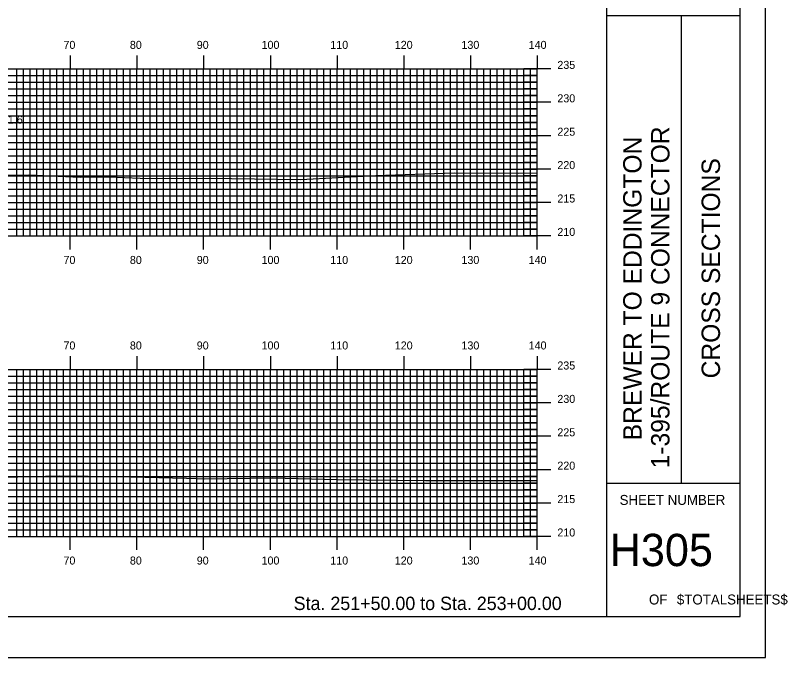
# Model space of a CAD drawing. Extents: x 1804290 to 1804634, y 442591 to 442811.
# Drawn here: x 1804518 to 1804633.7, y 442590.5 to 442686.7 of the extents above; entities that cross this region are included whole.
import ezdxf

# ---------------------------------------------------------------- set-up
doc = ezdxf.new("R2010")
doc.units = 0
for name, color, linetype in [('BORDER', 7, 'Continuous'), ('D_Text_Standard', 7, 'Continuous'), ('H_V ANNOTATION', 7, 'Continuous'), ('MAJOR', 7, 'Continuous'), ('MINOR', 7, 'Continuous'), ('PLOT BOUNDARY', 7, 'Continuous'), ('S_Roadway_Centerline', 7, 'Continuous')]:
    doc.layers.add(name, color=color, linetype=linetype)

msp = doc.modelspace()

# ---------------------------------------------------------------- linework, layer by layer
at = {"layer": 'BORDER'}
for p, q in [((1804606.57, 442596.67), (1804606.57, 442806.67)), ((1804606.57, 442686.67), (1804626.57, 442686.67)), ((1804617.75, 442616.67), (1804617.75, 442686.67)), ((1804606.57, 442616.67), (1804626.57, 442616.67))]:
    msp.add_line(p, q, dxfattribs=at)
msp.add_lwpolyline([(1804306.57, 442596.67), (1804626.57, 442596.67), (1804626.57, 442806.67), (1804306.57, 442806.67)], close=True, dxfattribs=at)
at = {"layer": 'MAJOR'}
for p, q in [((1804526.17, 442680.67), (1804526.17, 442678.67)), ((1804536.17, 442680.67), (1804536.17, 442678.67)), ((1804546.17, 442680.67), (1804546.17, 442678.67)), ((1804556.17, 442680.67), (1804556.17, 442678.67)), ((1804566.17, 442680.67), (1804566.17, 442678.67)), ((1804576.17, 442680.67), (1804576.17, 442678.67)), ((1804586.17, 442680.67), (1804586.17, 442678.67)), ((1804596.17, 442680.67), (1804596.17, 442678.67)), ((1804316.17, 442678.67), (1804596.17, 442678.67)), ((1804316.17, 442678.67), (1804596.17, 442678.67)), ((1804526.17, 442653.67), (1804526.17, 442678.67)), ((1804536.17, 442653.67), (1804536.17, 442678.67)), ((1804546.17, 442653.67), (1804546.17, 442678.67)), ((1804556.17, 442653.67), (1804556.17, 442678.67)), ((1804566.17, 442653.67), (1804566.17, 442678.67)), ((1804576.17, 442653.67), (1804576.17, 442678.67)), ((1804586.17, 442653.67), (1804586.17, 442678.67)), ((1804598.17, 442678.67), (1804594.16, 442678.67)), ((1804596.17, 442653.67), (1804596.17, 442678.67)), ((1804596.17, 442653.67), (1804596.17, 442678.67)), ((1804316.17, 442673.67), (1804596.17, 442673.67)), ((1804598.17, 442673.67), (1804594.16, 442673.67)), ((1804316.17, 442668.67), (1804596.17, 442668.67)), ((1804598.17, 442668.67), (1804594.16, 442668.67)), ((1804316.17, 442663.67), (1804596.17, 442663.67)), ((1804598.17, 442663.67), (1804594.16, 442663.67)), ((1804316.17, 442658.67), (1804596.17, 442658.67)), ((1804598.17, 442658.67), (1804594.16, 442658.67)), ((1804316.17, 442653.67), (1804596.17, 442653.67)), ((1804316.17, 442653.67), (1804596.17, 442653.67)), ((1804526.17, 442651.66), (1804526.17, 442653.67)), ((1804536.17, 442651.66), (1804536.17, 442653.67)), ((1804546.17, 442651.66), (1804546.17, 442653.67)), ((1804556.17, 442651.66), (1804556.17, 442653.67)), ((1804566.17, 442651.66), (1804566.17, 442653.67)), ((1804576.17, 442651.66), (1804576.17, 442653.67)), ((1804586.17, 442651.66), (1804586.17, 442653.67)), ((1804598.17, 442653.67), (1804594.16, 442653.67)), ((1804596.17, 442651.66), (1804596.17, 442653.67)), ((1804526.17, 442635.67), (1804526.17, 442633.67)), ((1804536.17, 442635.67), (1804536.17, 442633.67)), ((1804546.17, 442635.67), (1804546.17, 442633.67)), ((1804556.17, 442635.67), (1804556.17, 442633.67)), ((1804566.17, 442635.67), (1804566.17, 442633.67)), ((1804576.17, 442635.67), (1804576.17, 442633.67)), ((1804586.17, 442635.67), (1804586.17, 442633.67)), ((1804596.17, 442635.67), (1804596.17, 442633.67)), ((1804316.17, 442633.67), (1804596.17, 442633.67)), ((1804316.17, 442633.67), (1804596.17, 442633.67)), ((1804526.17, 442608.67), (1804526.17, 442633.67)), ((1804536.17, 442608.67), (1804536.17, 442633.67)), ((1804546.17, 442608.67), (1804546.17, 442633.67)), ((1804556.17, 442608.67), (1804556.17, 442633.67)), ((1804566.17, 442608.67), (1804566.17, 442633.67)), ((1804576.17, 442608.67), (1804576.17, 442633.67)), ((1804586.17, 442608.67), (1804586.17, 442633.67)), ((1804598.17, 442633.67), (1804594.16, 442633.67)), ((1804596.17, 442608.67), (1804596.17, 442633.67)), ((1804596.17, 442608.67), (1804596.17, 442633.67)), ((1804316.17, 442628.67), (1804596.17, 442628.67)), ((1804598.17, 442628.67), (1804594.16, 442628.67)), ((1804316.17, 442623.67), (1804596.17, 442623.67)), ((1804598.17, 442623.67), (1804594.16, 442623.67)), ((1804316.17, 442618.67), (1804596.17, 442618.67)), ((1804598.17, 442618.67), (1804594.16, 442618.67)), ((1804316.17, 442613.67), (1804596.17, 442613.67)), ((1804598.17, 442613.67), (1804594.16, 442613.67)), ((1804316.17, 442608.67), (1804596.17, 442608.67)), ((1804316.17, 442608.67), (1804596.17, 442608.67)), ((1804526.17, 442606.66), (1804526.17, 442608.67)), ((1804536.17, 442606.66), (1804536.17, 442608.67)), ((1804546.17, 442606.66), (1804546.17, 442608.67)), ((1804556.17, 442606.66), (1804556.17, 442608.67)), ((1804566.17, 442606.66), (1804566.17, 442608.67)), ((1804576.17, 442606.66), (1804576.17, 442608.67)), ((1804586.17, 442606.66), (1804586.17, 442608.67)), ((1804598.17, 442608.67), (1804594.16, 442608.67)), ((1804596.17, 442606.66), (1804596.17, 442608.67))]:
    msp.add_line(p, q, dxfattribs=at)
at = {"layer": 'MINOR'}
for p, q in [((1804316.17, 442677.67), (1804596.17, 442677.67)), ((1804518.17, 442653.67), (1804518.17, 442678.67)), ((1804519.17, 442653.67), (1804519.17, 442678.67)), ((1804520.17, 442653.67), (1804520.17, 442678.67)), ((1804521.17, 442653.67), (1804521.17, 442678.67)), ((1804522.17, 442653.67), (1804522.17, 442678.67)), ((1804523.17, 442653.67), (1804523.17, 442678.67)), ((1804524.17, 442653.67), (1804524.17, 442678.67)), ((1804525.17, 442653.67), (1804525.17, 442678.67)), ((1804527.17, 442653.67), (1804527.17, 442678.67)), ((1804528.17, 442653.67), (1804528.17, 442678.67)), ((1804529.17, 442653.67), (1804529.17, 442678.67)), ((1804530.17, 442653.67), (1804530.17, 442678.67)), ((1804531.17, 442653.67), (1804531.17, 442678.67)), ((1804532.17, 442653.67), (1804532.17, 442678.67)), ((1804533.17, 442653.67), (1804533.17, 442678.67)), ((1804534.17, 442653.67), (1804534.17, 442678.67)), ((1804535.17, 442653.67), (1804535.17, 442678.67)), ((1804537.17, 442653.67), (1804537.17, 442678.67)), ((1804538.17, 442653.67), (1804538.17, 442678.67)), ((1804539.17, 442653.67), (1804539.17, 442678.67)), ((1804540.17, 442653.67), (1804540.17, 442678.67)), ((1804541.17, 442653.67), (1804541.17, 442678.67)), ((1804542.17, 442653.67), (1804542.17, 442678.67)), ((1804543.17, 442653.67), (1804543.17, 442678.67)), ((1804544.17, 442653.67), (1804544.17, 442678.67)), ((1804545.17, 442653.67), (1804545.17, 442678.67)), ((1804547.17, 442653.67), (1804547.17, 442678.67)), ((1804548.17, 442653.67), (1804548.17, 442678.67)), ((1804549.17, 442653.67), (1804549.17, 442678.67)), ((1804550.17, 442653.67), (1804550.17, 442678.67)), ((1804551.17, 442653.67), (1804551.17, 442678.67)), ((1804552.17, 442653.67), (1804552.17, 442678.67)), ((1804553.17, 442653.67), (1804553.17, 442678.67)), ((1804554.17, 442653.67), (1804554.17, 442678.67)), ((1804555.17, 442653.67), (1804555.17, 442678.67)), ((1804557.17, 442653.67), (1804557.17, 442678.67)), ((1804558.17, 442653.67), (1804558.17, 442678.67)), ((1804559.17, 442653.67), (1804559.17, 442678.67)), ((1804560.17, 442653.67), (1804560.17, 442678.67)), ((1804561.17, 442653.67), (1804561.17, 442678.67)), ((1804562.17, 442653.67), (1804562.17, 442678.67)), ((1804563.17, 442653.67), (1804563.17, 442678.67)), ((1804564.17, 442653.67), (1804564.17, 442678.67)), ((1804565.17, 442653.67), (1804565.17, 442678.67)), ((1804567.17, 442653.67), (1804567.17, 442678.67)), ((1804568.17, 442653.67), (1804568.17, 442678.67)), ((1804569.17, 442653.67), (1804569.17, 442678.67)), ((1804570.17, 442653.67), (1804570.17, 442678.67)), ((1804571.17, 442653.67), (1804571.17, 442678.67)), ((1804572.17, 442653.67), (1804572.17, 442678.67)), ((1804573.17, 442653.67), (1804573.17, 442678.67)), ((1804574.17, 442653.67), (1804574.17, 442678.67)), ((1804575.17, 442653.67), (1804575.17, 442678.67)), ((1804577.17, 442653.67), (1804577.17, 442678.67)), ((1804578.17, 442653.67), (1804578.17, 442678.67)), ((1804579.17, 442653.67), (1804579.17, 442678.67)), ((1804580.17, 442653.67), (1804580.17, 442678.67)), ((1804581.17, 442653.67), (1804581.17, 442678.67)), ((1804582.17, 442653.67), (1804582.17, 442678.67)), ((1804583.17, 442653.67), (1804583.17, 442678.67)), ((1804584.17, 442653.67), (1804584.17, 442678.67)), ((1804585.17, 442653.67), (1804585.17, 442678.67)), ((1804587.17, 442653.67), (1804587.17, 442678.67)), ((1804588.17, 442653.67), (1804588.17, 442678.67)), ((1804589.17, 442653.67), (1804589.17, 442678.67)), ((1804590.17, 442653.67), (1804590.17, 442678.67)), ((1804591.17, 442653.67), (1804591.17, 442678.67)), ((1804592.17, 442653.67), (1804592.17, 442678.67)), ((1804593.17, 442653.67), (1804593.17, 442678.67)), ((1804596.17, 442677.67), (1804594.16, 442677.67)), ((1804594.17, 442653.67), (1804594.17, 442678.67)), ((1804595.17, 442653.67), (1804595.17, 442678.67)), ((1804316.17, 442676.67), (1804596.17, 442676.67)), ((1804596.17, 442676.67), (1804594.16, 442676.67)), ((1804316.17, 442675.67), (1804596.17, 442675.67)), ((1804596.17, 442675.67), (1804594.16, 442675.67)), ((1804316.17, 442674.67), (1804596.17, 442674.67)), ((1804596.17, 442674.67), (1804594.16, 442674.67)), ((1804316.17, 442672.67), (1804596.17, 442672.67)), ((1804596.17, 442672.67), (1804594.16, 442672.67)), ((1804316.17, 442671.67), (1804596.17, 442671.67)), ((1804316.17, 442670.67), (1804596.17, 442670.67)), ((1804596.17, 442671.67), (1804594.16, 442671.67)), ((1804596.17, 442670.67), (1804594.16, 442670.67)), ((1804316.17, 442669.67), (1804596.17, 442669.67)), ((1804596.17, 442669.67), (1804594.16, 442669.67)), ((1804316.17, 442667.67), (1804596.17, 442667.67)), ((1804596.17, 442667.67), (1804594.16, 442667.67)), ((1804316.17, 442666.67), (1804596.17, 442666.67)), ((1804596.17, 442666.67), (1804594.16, 442666.67)), ((1804316.17, 442665.67), (1804596.17, 442665.67)), ((1804596.17, 442665.67), (1804594.16, 442665.67)), ((1804316.17, 442664.67), (1804596.17, 442664.67)), ((1804596.17, 442664.67), (1804594.16, 442664.67)), ((1804316.17, 442662.67), (1804596.17, 442662.67)), ((1804596.17, 442662.67), (1804594.16, 442662.67)), ((1804316.17, 442661.67), (1804596.17, 442661.67)), ((1804596.17, 442661.67), (1804594.16, 442661.67)), ((1804316.17, 442660.67), (1804596.17, 442660.67)), ((1804596.17, 442660.67), (1804594.16, 442660.67)), ((1804316.17, 442659.67), (1804596.17, 442659.67)), ((1804596.17, 442659.67), (1804594.16, 442659.67)), ((1804316.17, 442657.67), (1804596.17, 442657.67)), ((1804596.17, 442657.67), (1804594.16, 442657.67)), ((1804316.17, 442656.67), (1804596.17, 442656.67)), ((1804316.17, 442655.67), (1804596.17, 442655.67)), ((1804596.17, 442656.67), (1804594.16, 442656.67)), ((1804596.17, 442655.67), (1804594.16, 442655.67)), ((1804316.17, 442654.67), (1804596.17, 442654.67)), ((1804596.17, 442654.67), (1804594.16, 442654.67)), ((1804518.17, 442608.67), (1804518.17, 442633.67)), ((1804519.17, 442608.67), (1804519.17, 442633.67)), ((1804520.17, 442608.67), (1804520.17, 442633.67)), ((1804521.17, 442608.67), (1804521.17, 442633.67)), ((1804522.17, 442608.67), (1804522.17, 442633.67)), ((1804523.17, 442608.67), (1804523.17, 442633.67)), ((1804524.17, 442608.67), (1804524.17, 442633.67)), ((1804525.17, 442608.67), (1804525.17, 442633.67)), ((1804527.17, 442608.67), (1804527.17, 442633.67)), ((1804528.17, 442608.67), (1804528.17, 442633.67)), ((1804529.17, 442608.67), (1804529.17, 442633.67)), ((1804530.17, 442608.67), (1804530.17, 442633.67)), ((1804531.17, 442608.67), (1804531.17, 442633.67)), ((1804532.17, 442608.67), (1804532.17, 442633.67)), ((1804533.17, 442608.67), (1804533.17, 442633.67)), ((1804534.17, 442608.67), (1804534.17, 442633.67)), ((1804535.17, 442608.67), (1804535.17, 442633.67)), ((1804537.17, 442608.67), (1804537.17, 442633.67)), ((1804538.17, 442608.67), (1804538.17, 442633.67)), ((1804539.17, 442608.67), (1804539.17, 442633.67)), ((1804540.17, 442608.67), (1804540.17, 442633.67)), ((1804541.17, 442608.67), (1804541.17, 442633.67)), ((1804542.17, 442608.67), (1804542.17, 442633.67)), ((1804543.17, 442608.67), (1804543.17, 442633.67)), ((1804544.17, 442608.67), (1804544.17, 442633.67)), ((1804545.17, 442608.67), (1804545.17, 442633.67)), ((1804547.17, 442608.67), (1804547.17, 442633.67)), ((1804548.17, 442608.67), (1804548.17, 442633.67)), ((1804549.17, 442608.67), (1804549.17, 442633.67)), ((1804550.17, 442608.67), (1804550.17, 442633.67)), ((1804551.17, 442608.67), (1804551.17, 442633.67)), ((1804552.17, 442608.67), (1804552.17, 442633.67)), ((1804553.17, 442608.67), (1804553.17, 442633.67)), ((1804554.17, 442608.67), (1804554.17, 442633.67)), ((1804555.17, 442608.67), (1804555.17, 442633.67)), ((1804557.17, 442608.67), (1804557.17, 442633.67)), ((1804558.17, 442608.67), (1804558.17, 442633.67)), ((1804559.17, 442608.67), (1804559.17, 442633.67)), ((1804560.17, 442608.67), (1804560.17, 442633.67)), ((1804561.17, 442608.67), (1804561.17, 442633.67)), ((1804562.17, 442608.67), (1804562.17, 442633.67)), ((1804563.17, 442608.67), (1804563.17, 442633.67)), ((1804564.17, 442608.67), (1804564.17, 442633.67)), ((1804565.17, 442608.67), (1804565.17, 442633.67)), ((1804567.17, 442608.67), (1804567.17, 442633.67)), ((1804568.17, 442608.67), (1804568.17, 442633.67)), ((1804569.17, 442608.67), (1804569.17, 442633.67)), ((1804570.17, 442608.67), (1804570.17, 442633.67)), ((1804571.17, 442608.67), (1804571.17, 442633.67)), ((1804572.17, 442608.67), (1804572.17, 442633.67)), ((1804573.17, 442608.67), (1804573.17, 442633.67)), ((1804574.17, 442608.67), (1804574.17, 442633.67)), ((1804575.17, 442608.67), (1804575.17, 442633.67)), ((1804577.17, 442608.67), (1804577.17, 442633.67)), ((1804578.17, 442608.67), (1804578.17, 442633.67)), ((1804579.17, 442608.67), (1804579.17, 442633.67)), ((1804580.17, 442608.67), (1804580.17, 442633.67)), ((1804581.17, 442608.67), (1804581.17, 442633.67)), ((1804582.17, 442608.67), (1804582.17, 442633.67)), ((1804583.17, 442608.67), (1804583.17, 442633.67)), ((1804584.17, 442608.67), (1804584.17, 442633.67)), ((1804585.17, 442608.67), (1804585.17, 442633.67)), ((1804587.17, 442608.67), (1804587.17, 442633.67)), ((1804588.17, 442608.67), (1804588.17, 442633.67)), ((1804589.17, 442608.67), (1804589.17, 442633.67)), ((1804590.17, 442608.67), (1804590.17, 442633.67)), ((1804591.17, 442608.67), (1804591.17, 442633.67)), ((1804592.17, 442608.67), (1804592.17, 442633.67)), ((1804593.17, 442608.67), (1804593.17, 442633.67)), ((1804594.17, 442608.67), (1804594.17, 442633.67)), ((1804595.17, 442608.67), (1804595.17, 442633.67)), ((1804316.17, 442632.67), (1804596.17, 442632.67)), ((1804596.17, 442632.67), (1804594.16, 442632.67)), ((1804316.17, 442631.67), (1804596.17, 442631.67)), ((1804596.17, 442631.67), (1804594.16, 442631.67)), ((1804316.17, 442630.67), (1804596.17, 442630.67)), ((1804596.17, 442630.67), (1804594.16, 442630.67)), ((1804316.17, 442629.67), (1804596.17, 442629.67)), ((1804596.17, 442629.67), (1804594.16, 442629.67)), ((1804316.17, 442627.67), (1804596.17, 442627.67)), ((1804596.17, 442627.67), (1804594.16, 442627.67)), ((1804316.17, 442626.67), (1804596.17, 442626.67)), ((1804316.17, 442625.67), (1804596.17, 442625.67)), ((1804596.17, 442626.67), (1804594.16, 442626.67)), ((1804596.17, 442625.67), (1804594.16, 442625.67)), ((1804316.17, 442624.67), (1804596.17, 442624.67)), ((1804596.17, 442624.67), (1804594.16, 442624.67)), ((1804316.17, 442622.67), (1804596.17, 442622.67)), ((1804596.17, 442622.67), (1804594.16, 442622.67)), ((1804316.17, 442621.67), (1804596.17, 442621.67)), ((1804596.17, 442621.67), (1804594.16, 442621.67)), ((1804316.17, 442620.67), (1804596.17, 442620.67)), ((1804596.17, 442620.67), (1804594.16, 442620.67)), ((1804316.17, 442619.67), (1804596.17, 442619.67)), ((1804596.17, 442619.67), (1804594.16, 442619.67)), ((1804316.17, 442617.67), (1804596.17, 442617.67)), ((1804596.17, 442617.67), (1804594.16, 442617.67)), ((1804316.17, 442616.67), (1804596.17, 442616.67)), ((1804596.17, 442616.67), (1804594.16, 442616.67)), ((1804316.17, 442615.67), (1804596.17, 442615.67)), ((1804596.17, 442615.67), (1804594.16, 442615.67)), ((1804316.17, 442614.67), (1804596.17, 442614.67)), ((1804596.17, 442614.67), (1804594.16, 442614.67)), ((1804316.17, 442612.67), (1804596.17, 442612.67)), ((1804316.17, 442611.67), (1804596.17, 442611.67)), ((1804596.17, 442612.67), (1804594.16, 442612.67)), ((1804596.17, 442611.67), (1804594.16, 442611.67)), ((1804316.17, 442610.67), (1804596.17, 442610.67)), ((1804596.17, 442610.67), (1804594.16, 442610.67)), ((1804316.17, 442609.67), (1804596.17, 442609.67)), ((1804596.17, 442609.67), (1804594.16, 442609.67))]:
    msp.add_line(p, q, dxfattribs=at)
at = {"layer": 'PLOT BOUNDARY'}
msp.add_lwpolyline([(1804290.38, 442590.55), (1804630.38, 442590.55), (1804630.38, 442810.55), (1804290.38, 442810.55)], close=True, dxfattribs=at)
at = {"layer": 'S_Roadway_Centerline'}
for points in [[(1804511.41, 442662.7), (1804519.93, 442662.8), (1804527.67, 442662.48), (1804531.95, 442662.49), (1804536.67, 442662.33), (1804550.33, 442662.27), (1804560.67, 442662.11), (1804571.99, 442662.69), (1804583.7, 442663.12), (1804593.4, 442663.05), (1804596.17, 442663.13)], [(1804509.97, 442617.38), (1804524.54, 442617.77), (1804533.19, 442617.63), (1804543.6, 442617.39), (1804545.06, 442617.34), (1804546.35, 442617.32), (1804556.46, 442617.45), (1804566.25, 442617.22), (1804579.42, 442617.06), (1804591.16, 442617.03), (1804591.58, 442617.03), (1804596.17, 442617.03)]]:
    msp.add_lwpolyline(points, dxfattribs=at)

# ---------------------------------------------------------------- texts
at = {"layer": 'BORDER'}
for s, p in [('1-395/ROUTE 9 CONNECTOR', (1804615.97, 442618.87)), ('BREWER TO EDDINGTON', (1804611.79, 442623.07)), ('CROSS SECTIONS', (1804623.54, 442632.34))]:
    msp.add_text(s, height=2.7557, rotation=90, dxfattribs=at).set_placement(p)
for s, height, p in [('SHEET NUMBER', 1.4905, (1804608.5, 442613.4)), ('H305', 4.839, (1804607.01, 442604.23)), ('$TOTALSHEETS$', 1.4905, (1804617.08, 442598.49)), ('OF', 1.491, (1804612.9, 442598.49))]:
    msp.add_text(s, height=height, dxfattribs=at).set_placement(p)
at = {"layer": 'D_Text_Standard'}
msp.add_text("61.6'", height=1.2, dxfattribs=at).set_placement((1804515.94, 442670.48))
at = {"layer": 'H_V ANNOTATION'}
for s, height, p in [('70', 1.2, (1804525.17, 442681.67)), ('80', 1.2, (1804535.12, 442681.67)), ('90', 1.2, (1804545.14, 442681.67)), ('100', 1.2, (1804554.85, 442681.67)), ('110', 1.2, (1804565.15, 442681.67)), ('120', 1.2, (1804574.81, 442681.67)), ('130', 1.2, (1804584.8, 442681.67)), ('140', 1.2, (1804594.87, 442681.67)), ('235', 1.2, (1804599.17, 442678.67)), ('230', 1.2, (1804599.17, 442673.67)), ('225', 1.2, (1804599.17, 442668.67)), ('220', 1.2, (1804599.17, 442663.67)), ('215', 1.2, (1804599.17, 442658.67)), ('210', 1.2, (1804599.17, 442653.67)), ('70', 1.2, (1804525.17, 442649.47)), ('80', 1.2, (1804535.12, 442649.47)), ('90', 1.2, (1804545.14, 442649.47)), ('100', 1.2, (1804554.85, 442649.47)), ('110', 1.2, (1804565.15, 442649.47)), ('120', 1.2, (1804574.81, 442649.47)), ('130', 1.2, (1804584.8, 442649.47)), ('140', 1.2, (1804594.87, 442649.47)), ('70', 1.2, (1804525.17, 442636.67)), ('80', 1.2, (1804535.12, 442636.67)), ('90', 1.2, (1804545.14, 442636.67)), ('100', 1.2, (1804554.85, 442636.67)), ('110', 1.2, (1804565.15, 442636.67)), ('120', 1.2, (1804574.81, 442636.67)), ('130', 1.2, (1804584.8, 442636.67)), ('140', 1.2, (1804594.87, 442636.67)), ('235', 1.2, (1804599.17, 442633.67)), ('230', 1.2, (1804599.17, 442628.67)), ('225', 1.2, (1804599.17, 442623.67)), ('220', 1.2, (1804599.17, 442618.67)), ('215', 1.2, (1804599.17, 442613.67)), ('210', 1.2, (1804599.17, 442608.67)), ('70', 1.2, (1804525.17, 442604.47)), ('80', 1.2, (1804535.12, 442604.47)), ('90', 1.2, (1804545.14, 442604.47)), ('100', 1.2, (1804554.85, 442604.47)), ('110', 1.2, (1804565.15, 442604.47)), ('120', 1.2, (1804574.81, 442604.47)), ('130', 1.2, (1804584.8, 442604.47)), ('140', 1.2, (1804594.87, 442604.47)), ('Sta. 251+50.00 to Sta. 253+00.00', 2.0004, (1804559.66, 442597.66))]:
    msp.add_text(s, height=height, dxfattribs=at).set_placement(p)

doc.saveas('drawing.dxf')
